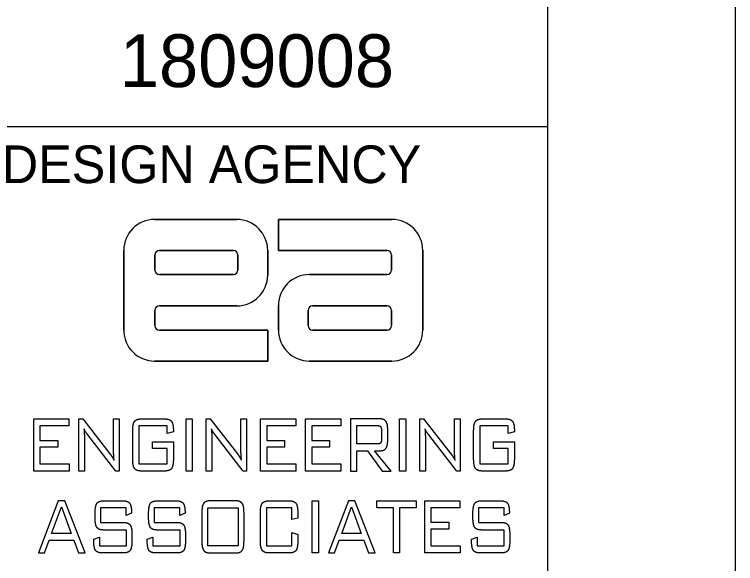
# Model space of a CAD drawing. Extents: x 0 to 34, y 0 to 22.
# Drawn here: x 32.083 to 34, y 3.84 to 5.298 of the extents above; entities that cross this region are included whole.
import ezdxf

# ---------------------------------------------------------------- set-up
doc = ezdxf.new("R2010")
doc.units = 0
for name, color, linetype in [('SH_Border', 7, 'Continuous'), ('SH_Cut_Line', 7, 'Continuous'), ('SH_Data', 7, 'Continuous'), ('TX_X_20', 7, 'Continuous')]:
    doc.layers.add(name, color=color, linetype=linetype)

msp = doc.modelspace()

# ---------------------------------------------------------------- linework, layer by layer
at = {"layer": 'SH_Border'}
msp.add_line((32, 5), (33.5, 5), dxfattribs=at)
msp.add_lwpolyline([(1.5, 21.5), (33.5, 21.5), (33.5, 0.5), (1.5, 0.5)], close=True, dxfattribs=at)
at = {"layer": 'SH_Cut_Line'}
msp.add_lwpolyline([(0, 0), (34, 0), (34, 22), (0, 22)], close=True, dxfattribs=at)
at = {"layer": 'SH_Data'}
msp.add_line((32.75, 4), (32.75, 4), dxfattribs=at)
at = {"layer": 'TX_X_20'}
for p, q in [((32.6745, 4.7533), (32.456, 4.7533)), ((32.456, 4.7533), (32.6745, 4.7533)), ((32.785, 4.7533), (33.0865, 4.7533)), ((32.785, 4.6713), (32.785, 4.7533)), ((32.3739, 4.6713), (32.3739, 4.4597)), ((32.3739, 4.4597), (32.3739, 4.6713)), ((32.457, 4.6189), (32.457, 4.6594)), ((32.457, 4.6594), (32.457, 4.6189)), ((32.4688, 4.6713), (32.6656, 4.6713)), ((32.6656, 4.6713), (32.4688, 4.6713)), ((32.6775, 4.6594), (32.6775, 4.6189)), ((32.6775, 4.6189), (32.6775, 4.6594)), ((32.7566, 4.606), (32.7566, 4.6713)), ((32.7566, 4.6713), (32.7566, 4.606)), ((33.0737, 4.6713), (32.785, 4.6713)), ((33.0855, 4.6594), (33.0855, 4.6189)), ((33.0855, 4.6189), (33.0855, 4.6594)), ((33.1686, 4.4597), (33.1686, 4.6713)), ((33.1686, 4.6713), (33.1686, 4.4597)), ((32.6656, 4.607), (32.4688, 4.607)), ((32.4688, 4.607), (32.6656, 4.607)), ((33.0737, 4.607), (32.8671, 4.607)), ((32.8671, 4.607), (33.0737, 4.607)), ((32.4688, 4.524), (32.6745, 4.524)), ((32.6745, 4.524), (32.4688, 4.524)), ((32.785, 4.525), (32.785, 4.4597)), ((32.785, 4.4597), (32.785, 4.525)), ((32.876, 4.524), (33.0737, 4.524)), ((33.0737, 4.524), (32.876, 4.524)), ((32.457, 4.4716), (32.457, 4.5121)), ((32.457, 4.5121), (32.457, 4.4716)), ((32.8641, 4.4716), (32.8641, 4.5121)), ((32.8641, 4.5121), (32.8641, 4.4716)), ((33.0855, 4.5121), (33.0855, 4.4716)), ((33.0855, 4.4716), (33.0855, 4.5121)), ((32.4688, 4.4597), (32.7566, 4.4597)), ((32.7566, 4.4597), (32.7566, 4.3777)), ((33.0737, 4.4597), (32.876, 4.4597)), ((32.876, 4.4597), (33.0737, 4.4597)), ((32.7566, 4.3777), (32.456, 4.3777)), ((32.8671, 4.3777), (33.0865, 4.3777)), ((33.0865, 4.3777), (32.8671, 4.3777)), ((32.4205, 4.224), (32.4832, 4.224)), ((33.3267, 4.224), (33.3893, 4.224)), ((32.3978, 4.1184), (32.3978, 4.1913)), ((33.0591, 4.1918), (33.0591, 4.1716)), ((33.0755, 4.1662), (33.0755, 4.1972)), ((33.3039, 4.1184), (33.3039, 4.1913)), ((32.4832, 4.0856), (32.4205, 4.0856)), ((33.3893, 4.0856), (33.3267, 4.0856)), ((32.3205, 4.0065), (32.3719, 4.0065)), ((32.4627, 4.0065), (32.5142, 4.0065)), ((32.6711, 4.0065), (32.6041, 4.0065)), ((32.7599, 4.0065), (32.814, 4.0065)), ((33.3246, 4.0065), (33.3761, 4.0065)), ((32.2979, 3.9618), (32.2979, 3.9738)), ((32.4401, 3.9618), (32.4401, 3.9738)), ((32.5814, 3.9738), (32.5814, 3.9009)), ((32.6936, 3.9009), (32.6936, 3.9738)), ((32.7371, 3.9009), (32.7371, 3.9738)), ((33.302, 3.9618), (33.302, 3.9738)), ((32.3958, 3.9164), (32.3958, 3.9009)), ((32.538, 3.9164), (32.538, 3.9009)), ((33.3999, 3.9164), (33.3999, 3.9009)), ((32.3733, 3.8681), (32.3169, 3.8681)), ((32.5155, 3.8681), (32.4591, 3.8681)), ((32.6041, 3.8681), (32.6711, 3.8681)), ((32.814, 3.8681), (32.7599, 3.8681)), ((33.3774, 3.8681), (33.321, 3.8681))]:
    msp.add_line(p, q, dxfattribs=at)
for points in [[(33.0865, 4.7533), (32.785, 4.7533), (32.785, 4.6713), (33.0737, 4.6713)], [(32.456, 4.3777), (32.7566, 4.3777), (32.7566, 4.4597), (32.4688, 4.4597)], [(32.2695, 4.1672), (32.2695, 4.0856), (32.2547, 4.0856), (32.2547, 4.224), (32.2649, 4.224), (32.3374, 4.1315)], [(32.3469, 4.1481), (32.3469, 4.224), (32.3617, 4.224), (32.3617, 4.0856), (32.3526, 4.0856), (32.2782, 4.1819)], [(32.608, 4.1672), (32.608, 4.0856), (32.5932, 4.0856), (32.5932, 4.224), (32.6034, 4.224), (32.6759, 4.1315)], [(32.6854, 4.1481), (32.6854, 4.224), (32.7002, 4.224), (32.7002, 4.0856), (32.6912, 4.0856), (32.6168, 4.1819)], [(33.055, 4.224), (32.9769, 4.224), (32.9769, 4.0856), (32.9932, 4.0856), (32.9932, 4.1395), (33.0217, 4.1395), (33.0611, 4.0856), (33.0851, 4.0856), (33.0408, 4.1395), (33.055, 4.1395)], [(33.1756, 4.1672), (33.1756, 4.0856), (33.1608, 4.0856), (33.1608, 4.224), (33.171, 4.224), (33.2435, 4.1315)], [(33.253, 4.1481), (33.253, 4.224), (33.2678, 4.224), (33.2678, 4.0856), (33.2588, 4.0856), (33.1844, 4.1819)], [(32.5059, 4.1929), (32.5059, 4.1895), (32.4898, 4.1849), (32.4898, 4.2052), (32.4139, 4.2052), (32.4139, 4.1049), (32.4898, 4.1049), (32.4898, 4.1456), (32.4506, 4.1456), (32.4506, 4.1632), (32.5059, 4.1632), (32.5059, 4.1184)], [(33.0487, 4.1574), (32.9932, 4.1574), (32.9932, 4.2062), (33.0487, 4.2062)], [(33.4121, 4.1929), (33.4121, 4.1895), (33.3959, 4.1849), (33.3959, 4.2052), (33.3201, 4.2052), (33.3201, 4.1049), (33.3959, 4.1049), (33.3959, 4.1456), (33.3567, 4.1456), (33.3567, 4.1632), (33.4121, 4.1632), (33.4121, 4.1184)], [(32.3947, 3.9762), (32.3947, 3.9733), (32.3808, 3.9676), (32.3808, 3.9877), (32.3124, 3.9877), (32.3124, 3.9491), (32.3733, 3.9491)], [(32.5369, 3.9762), (32.5369, 3.9733), (32.523, 3.9676), (32.523, 3.9877), (32.4546, 3.9877), (32.4546, 3.9491), (32.5155, 3.9491)], [(32.8366, 3.9738), (32.8366, 3.9608), (32.8204, 3.9565), (32.8204, 3.9877), (32.7533, 3.9877), (32.7533, 3.8874), (32.8204, 3.8874), (32.8204, 3.9221), (32.8366, 3.9172), (32.8366, 3.9009)], [(33.3988, 3.9762), (33.3988, 3.9733), (33.3849, 3.9676), (33.3849, 3.9877), (33.3165, 3.9877), (33.3165, 3.9491), (33.3774, 3.9491)], [(32.2942, 3.9009), (32.2942, 3.9047), (32.3092, 3.9096), (32.3092, 3.8874), (32.3813, 3.8874), (32.3813, 3.929), (32.3205, 3.929)], [(32.4364, 3.9009), (32.4364, 3.9047), (32.4514, 3.9096), (32.4514, 3.8874), (32.5235, 3.8874), (32.5235, 3.929), (32.4627, 3.929)], [(33.2983, 3.9009), (33.2983, 3.9047), (33.3133, 3.9096), (33.3133, 3.8874), (33.3854, 3.8874), (33.3854, 3.929), (33.3246, 3.929)]]:
    msp.add_lwpolyline(points, dxfattribs=at)
for points in [[(32.1351, 4.0856), (32.1351, 4.224), (32.2283, 4.224), (32.2283, 4.2055), (32.1513, 4.2055), (32.1513, 4.167), (32.1984, 4.167), (32.1984, 4.1487), (32.1513, 4.1487), (32.1513, 4.1046), (32.2291, 4.1046), (32.2291, 4.0856)], [(32.5396, 4.0856), (32.5396, 4.224), (32.5558, 4.224), (32.5558, 4.0856)], [(32.7376, 4.0856), (32.7376, 4.224), (32.8309, 4.224), (32.8309, 4.2055), (32.7539, 4.2055), (32.7539, 4.167), (32.801, 4.167), (32.801, 4.1487), (32.7539, 4.1487), (32.7539, 4.1046), (32.8316, 4.1046), (32.8316, 4.0856)], [(32.8573, 4.0856), (32.8573, 4.224), (32.9505, 4.224), (32.9505, 4.2055), (32.8735, 4.2055), (32.8735, 4.167), (32.9206, 4.167), (32.9206, 4.1487), (32.8735, 4.1487), (32.8735, 4.1046), (32.9513, 4.1046), (32.9513, 4.0856)], [(33.1072, 4.0856), (33.1072, 4.224), (33.1234, 4.224), (33.1234, 4.0856)], [(32.1472, 3.8681), (32.1631, 3.8681), (32.1755, 3.9023), (32.241, 3.9023), (32.2534, 3.8681), (32.2712, 3.8681), (32.2174, 4.0065), (32.2001, 4.0065)], [(32.875, 3.8681), (32.875, 4.0065), (32.8912, 4.0065), (32.8912, 3.8681)], [(32.9182, 3.8681), (32.9341, 3.8681), (32.9465, 3.9023), (33.012, 3.9023), (33.0244, 3.8681), (33.0422, 3.8681), (32.9884, 4.0065), (32.9711, 4.0065)], [(33.1068, 3.9877), (33.1068, 3.8681), (33.0907, 3.8681), (33.0907, 3.9877), (33.0464, 3.9877), (33.0464, 4.0065), (33.1513, 4.0065), (33.1513, 3.9877)], [(33.1742, 3.8681), (33.1742, 4.0065), (33.2675, 4.0065), (33.2675, 3.988), (33.1905, 3.988), (33.1905, 3.9495), (33.2376, 3.9495), (33.2376, 3.9312), (33.1905, 3.9312), (33.1905, 3.8871), (33.2682, 3.8871), (33.2682, 3.8681)], [(32.1823, 3.9199), (32.2083, 3.9907), (32.2344, 3.9199)], [(32.5975, 3.8874), (32.5975, 3.9877), (32.6777, 3.9877), (32.6777, 3.8874)], [(32.9533, 3.9199), (32.9793, 3.9907), (33.0054, 3.9199)]]:
    msp.add_lwpolyline(points, close=True, dxfattribs=at)
for centre, radius, start, end in [((32.456, 4.6713), 0.0821, 90, 180), ((32.456, 4.6713), 0.0821, 90, 180), ((32.6745, 4.6713), 0.0821, 0, 90), ((32.6745, 4.6713), 0.0821, 0, 90), ((33.0865, 4.6713), 0.0821, 0, 90), ((33.0865, 4.6713), 0.0821, 0, 90), ((32.4688, 4.6594), 0.0119, 90, 180), ((32.4688, 4.6594), 0.0119, 90, 180), ((32.6656, 4.6594), 0.0119, 0, 90), ((32.6656, 4.6594), 0.0119, 0, 90), ((33.0737, 4.6594), 0.0119, 0, 90), ((33.0737, 4.6594), 0.0119, 0, 90), ((32.4688, 4.6189), 0.0119, 180, 270), ((32.4688, 4.6189), 0.0119, 180, 270), ((32.6656, 4.6189), 0.0119, 270, 0), ((32.6656, 4.6189), 0.0119, 270, 0), ((32.6745, 4.606), 0.0821, 270, 360), ((32.6745, 4.606), 0.0821, 270, 360), ((32.8671, 4.525), 0.0821, 90, 180), ((32.8671, 4.525), 0.0821, 90, 180), ((33.0737, 4.6189), 0.0119, 270, 0), ((33.0737, 4.6189), 0.0119, 270, 0), ((32.4688, 4.5121), 0.0119, 90, 180), ((32.4688, 4.5121), 0.0119, 90, 180), ((32.876, 4.5121), 0.0119, 90, 180), ((32.876, 4.5121), 0.0119, 90, 180), ((33.0737, 4.5121), 0.0119, 0, 90), ((33.0737, 4.5121), 0.0119, 0, 90), ((32.4688, 4.4716), 0.0119, 180, 270), ((32.4688, 4.4716), 0.0119, 180, 270), ((32.876, 4.4716), 0.0119, 180, 270), ((32.876, 4.4716), 0.0119, 180, 270), ((33.0737, 4.4716), 0.0119, 270, 0), ((33.0737, 4.4716), 0.0119, 270, 0), ((32.456, 4.4597), 0.0821, 180, 270), ((32.456, 4.4597), 0.0821, 180, 270), ((32.8671, 4.4597), 0.0821, 180, 270), ((32.8671, 4.4597), 0.0821, 180, 270), ((33.0865, 4.4597), 0.0821, 270, 360), ((33.0865, 4.4597), 0.0821, 270, 360)]:
    msp.add_arc(centre, radius, start, end, dxfattribs=at)
for points in [[(32.3978, 4.1913), (32.3978, 4.2102), (32.4025, 4.2171)], [(32.4025, 4.2171), (32.4072, 4.224), (32.4205, 4.224)], [(32.4832, 4.224), (32.4962, 4.224), (32.5011, 4.2173)], [(32.5011, 4.2173), (32.5059, 4.2105), (32.5059, 4.1929)], [(33.0707, 4.2177), (33.0659, 4.224), (33.055, 4.224)], [(33.0755, 4.1972), (33.0755, 4.2113), (33.0707, 4.2177)], [(33.3039, 4.1913), (33.3039, 4.2102), (33.3086, 4.2171)], [(33.3086, 4.2171), (33.3134, 4.224), (33.3267, 4.224)], [(33.3893, 4.224), (33.4023, 4.224), (33.4072, 4.2173)], [(33.4072, 4.2173), (33.4121, 4.2105), (33.4121, 4.1929)], [(32.2766, 4.184), (32.2711, 4.191), (32.2684, 4.1975)], [(32.2684, 4.1975), (32.269, 4.1912), (32.2692, 4.184)], [(32.6151, 4.184), (32.6096, 4.191), (32.6069, 4.1975)], [(32.6069, 4.1975), (32.6075, 4.1912), (32.6078, 4.184)], [(33.0487, 4.2062), (33.0546, 4.2062), (33.0569, 4.2029)], [(33.0569, 4.2029), (33.0591, 4.1997), (33.0591, 4.1918)], [(33.1827, 4.184), (33.1772, 4.191), (33.1746, 4.1975)], [(33.1746, 4.1975), (33.1751, 4.1912), (33.1754, 4.184)], [(32.2692, 4.184), (32.2695, 4.1769), (32.2695, 4.1672)], [(32.2782, 4.1819), (32.2777, 4.1825), (32.2766, 4.184)], [(32.6078, 4.184), (32.608, 4.1769), (32.608, 4.1672)], [(32.6168, 4.1819), (32.6162, 4.1825), (32.6151, 4.184)], [(33.1754, 4.184), (33.1756, 4.1769), (33.1756, 4.1672)], [(33.1844, 4.1819), (33.1838, 4.1825), (33.1827, 4.184)], [(33.0569, 4.1606), (33.0547, 4.1574), (33.0487, 4.1574)], [(33.0591, 4.1716), (33.0591, 4.1637), (33.0569, 4.1606)], [(33.0707, 4.1459), (33.0755, 4.1522), (33.0755, 4.1662)], [(32.3473, 4.128), (32.3469, 4.1353), (32.3469, 4.1481)], [(32.6858, 4.128), (32.6854, 4.1353), (32.6854, 4.1481)], [(33.055, 4.1395), (33.0659, 4.1395), (33.0707, 4.1459)], [(33.2534, 4.128), (33.253, 4.1353), (33.253, 4.1481)], [(32.3374, 4.1315), (32.3398, 4.1283), (32.3426, 4.1239)], [(32.3426, 4.1239), (32.3454, 4.1194), (32.3484, 4.114)], [(32.3484, 4.114), (32.3476, 4.1207), (32.3473, 4.128)], [(32.6759, 4.1315), (32.6784, 4.1283), (32.6812, 4.1239)], [(32.6812, 4.1239), (32.684, 4.1194), (32.6869, 4.114)], [(32.6869, 4.114), (32.6862, 4.1207), (32.6858, 4.128)], [(33.2435, 4.1315), (33.246, 4.1283), (33.2488, 4.1239)], [(33.2488, 4.1239), (33.2516, 4.1194), (33.2545, 4.114)], [(33.2545, 4.114), (33.2538, 4.1207), (33.2534, 4.128)], [(32.4025, 4.0926), (32.3978, 4.0995), (32.3978, 4.1184)], [(32.5059, 4.1184), (32.5059, 4.0994), (32.5012, 4.0925)], [(33.3086, 4.0926), (33.3039, 4.0995), (33.3039, 4.1184)], [(33.4121, 4.1184), (33.4121, 4.0994), (33.4073, 4.0925)], [(32.4205, 4.0856), (32.4072, 4.0856), (32.4025, 4.0926)], [(32.5012, 4.0925), (32.4964, 4.0856), (32.4832, 4.0856)], [(33.3267, 4.0856), (33.3134, 4.0856), (33.3086, 4.0926)], [(33.4073, 4.0925), (33.4025, 4.0856), (33.3893, 4.0856)], [(32.3026, 3.9997), (32.3072, 4.0065), (32.3205, 4.0065)], [(32.3719, 4.0065), (32.3849, 4.0065), (32.3898, 3.9998)], [(32.4448, 3.9997), (32.4495, 4.0065), (32.4627, 4.0065)], [(32.5142, 4.0065), (32.5271, 4.0065), (32.532, 3.9998)], [(32.6041, 4.0065), (32.5908, 4.0065), (32.5861, 3.9996)], [(32.6889, 3.9997), (32.6842, 4.0065), (32.6711, 4.0065)], [(32.7419, 3.9997), (32.7467, 4.0065), (32.7599, 4.0065)], [(32.814, 4.0065), (32.8272, 4.0065), (32.8319, 3.9997)], [(33.3067, 3.9997), (33.3114, 4.0065), (33.3246, 4.0065)], [(33.3761, 4.0065), (33.389, 4.0065), (33.3939, 3.9998)], [(32.2979, 3.9738), (32.2979, 3.9928), (32.3026, 3.9997)], [(32.3898, 3.9998), (32.3947, 3.9931), (32.3947, 3.9762)], [(32.4401, 3.9738), (32.4401, 3.9928), (32.4448, 3.9997)], [(32.532, 3.9998), (32.5369, 3.9931), (32.5369, 3.9762)], [(32.5861, 3.9996), (32.5814, 3.9927), (32.5814, 3.9738)], [(32.6936, 3.9738), (32.6936, 3.9928), (32.6889, 3.9997)], [(32.7371, 3.9738), (32.7371, 3.9928), (32.7419, 3.9997)], [(32.8319, 3.9997), (32.8366, 3.9929), (32.8366, 3.9738)], [(33.302, 3.9738), (33.302, 3.9928), (33.3067, 3.9997)], [(33.3939, 3.9998), (33.3988, 3.9931), (33.3988, 3.9762)], [(32.3026, 3.9359), (32.2979, 3.9428), (32.2979, 3.9618)], [(32.3733, 3.9491), (32.3863, 3.9491), (32.391, 3.9423)], [(32.4448, 3.9359), (32.4401, 3.9428), (32.4401, 3.9618)], [(32.5155, 3.9491), (32.5285, 3.9491), (32.5333, 3.9423)], [(33.3067, 3.9359), (33.302, 3.9428), (33.302, 3.9618)], [(33.3774, 3.9491), (33.3904, 3.9491), (33.3952, 3.9423)], [(32.3205, 3.929), (32.3072, 3.929), (32.3026, 3.9359)], [(32.391, 3.9423), (32.3958, 3.9355), (32.3958, 3.9164)], [(32.4627, 3.929), (32.4495, 3.929), (32.4448, 3.9359)], [(32.5333, 3.9423), (32.538, 3.9355), (32.538, 3.9164)], [(33.3246, 3.929), (33.3114, 3.929), (33.3067, 3.9359)], [(33.3952, 3.9423), (33.3999, 3.9355), (33.3999, 3.9164)], [(32.2989, 3.875), (32.2942, 3.8819), (32.2942, 3.9009)], [(32.3958, 3.9009), (32.3958, 3.8818), (32.3911, 3.875)], [(32.4411, 3.875), (32.4364, 3.8819), (32.4364, 3.9009)], [(32.538, 3.9009), (32.538, 3.8818), (32.5333, 3.875)], [(32.5814, 3.9009), (32.5814, 3.882), (32.5861, 3.8751)], [(32.6889, 3.875), (32.6936, 3.8818), (32.6936, 3.9009)], [(32.7419, 3.875), (32.7371, 3.8819), (32.7371, 3.9009)], [(32.8366, 3.9009), (32.8366, 3.8818), (32.8319, 3.875)], [(33.3031, 3.875), (33.2983, 3.8819), (33.2983, 3.9009)], [(33.3999, 3.9009), (33.3999, 3.8818), (33.3953, 3.875)], [(32.3169, 3.8681), (32.3037, 3.8681), (32.2989, 3.875)], [(32.3911, 3.875), (32.3865, 3.8681), (32.3733, 3.8681)], [(32.4591, 3.8681), (32.4459, 3.8681), (32.4411, 3.875)], [(32.5333, 3.875), (32.5287, 3.8681), (32.5155, 3.8681)], [(32.5861, 3.8751), (32.5908, 3.8681), (32.6041, 3.8681)], [(32.6711, 3.8681), (32.6842, 3.8681), (32.6889, 3.875)], [(32.7599, 3.8681), (32.7467, 3.8681), (32.7419, 3.875)], [(32.8319, 3.875), (32.8272, 3.8681), (32.814, 3.8681)], [(33.321, 3.8681), (33.3078, 3.8681), (33.3031, 3.875)], [(33.3953, 3.875), (33.3906, 3.8681), (33.3774, 3.8681)]]:
    msp.add_open_spline(points, degree=2, dxfattribs=at)

# ---------------------------------------------------------------- texts
at = {"layer": 'SH_Data'}
for s, height, p in [('1809008', 0.14, (32.3635, 5.105)), ('DESIGN AGENCY', 0.1, (32.05, 4.85))]:
    msp.add_text(s, height=height, dxfattribs=at).set_placement(p)

doc.saveas('drawing.dxf')
